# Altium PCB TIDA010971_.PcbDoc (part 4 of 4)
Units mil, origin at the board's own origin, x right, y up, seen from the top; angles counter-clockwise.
Board outline 4500 x 6000 mil, 2 copper layers (F.CU, B.CU), stack 60.617 mil thick; 280 components, 124 nets, 681 pads, 871 vias.
Unrouted connection lines stored in the file: 1.
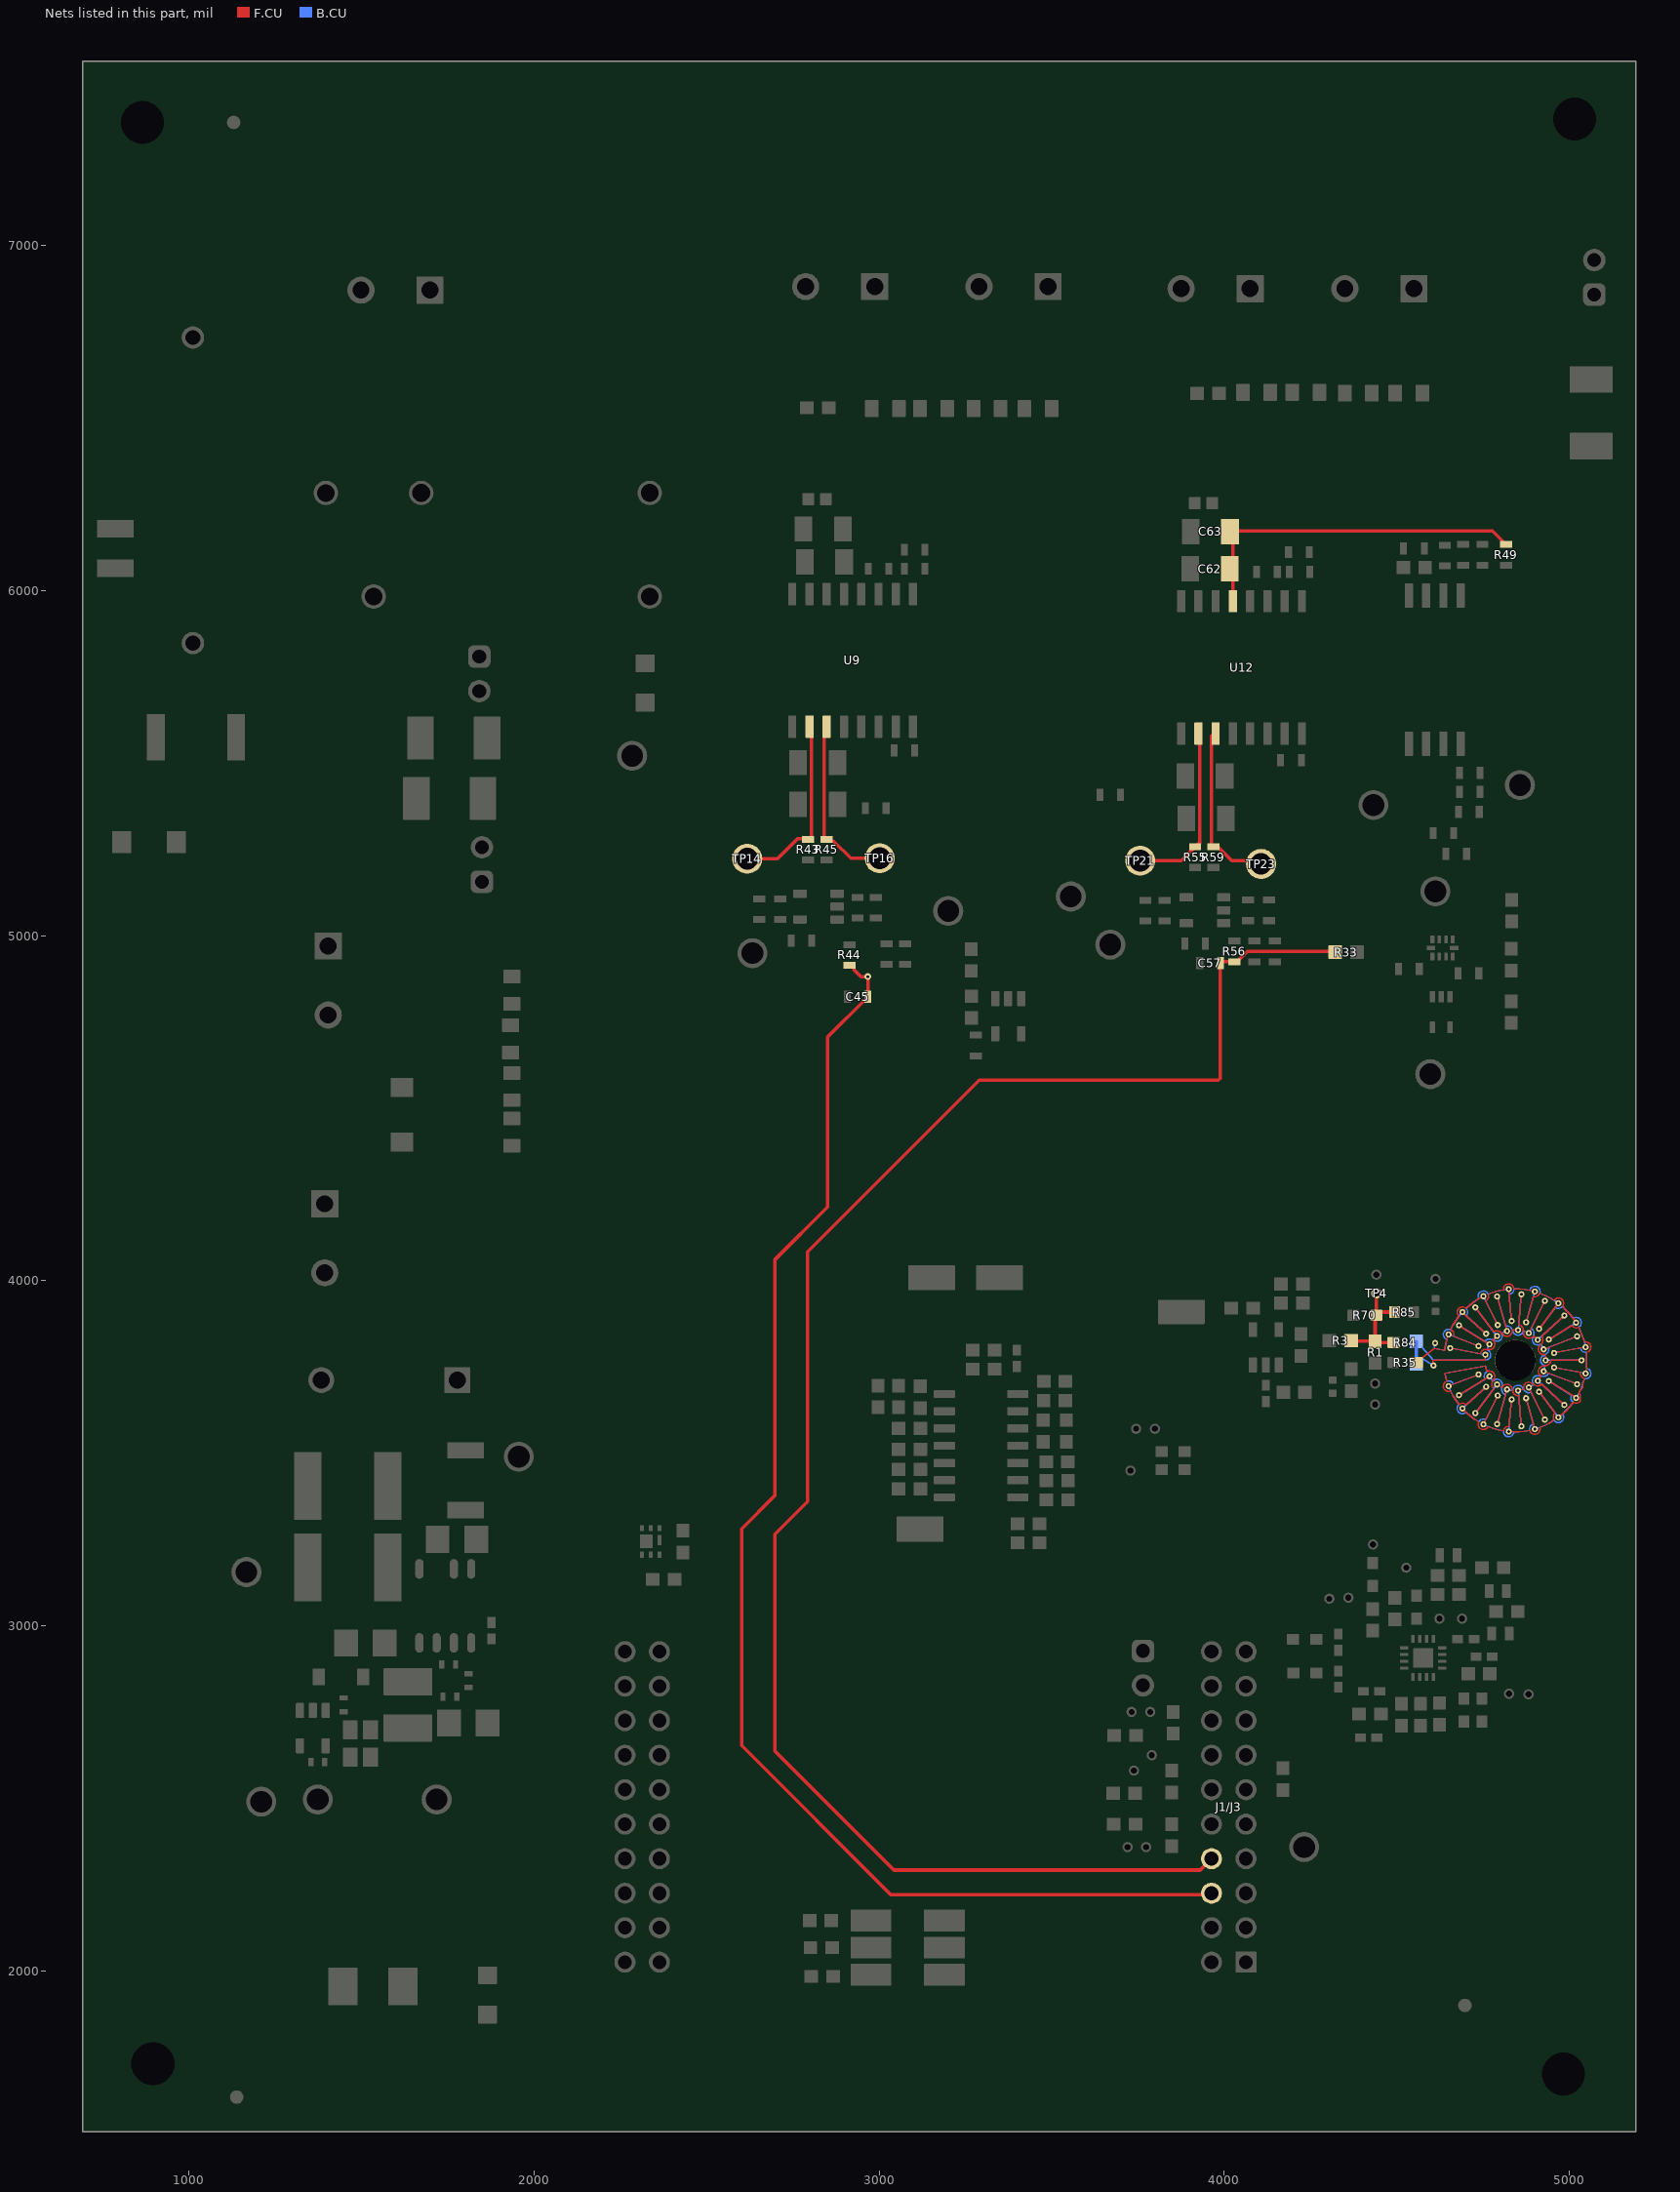
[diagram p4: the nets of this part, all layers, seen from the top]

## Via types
v1: diameter 24, hole 8, F.CU to B.CU, tented both sides, 774 vias
v2: diameter 19.68, hole 7.87, F.CU to B.CU, tented both sides, 97 vias

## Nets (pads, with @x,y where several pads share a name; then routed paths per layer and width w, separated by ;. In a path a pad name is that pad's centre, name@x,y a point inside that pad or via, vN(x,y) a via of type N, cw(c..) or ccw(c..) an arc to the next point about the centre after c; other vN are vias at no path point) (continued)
Rogo-: pad.1 pad.2 pad.3 pad.4 pad.12 pad.13 pad.14 pad.15 pad.16 pad.17 pad.18 pad.19 pad.20 pad.21 pad.22 pad.23 pad.24 pad.25 pad.26 pad.27 pad.28 pad.29 pad.30 pad.31 pad.32 pad.33 pad.34 pad.35 pad.36 pad.37 pad.38 pad.39 pad.40 pad.41 pad.42 pad.43 pad.44 pad.45 pad.46 pad.47 pad.48 pad.49 pad.50 pad.51 pad.52 pad.53 pad.54 pad.55 pad.56 pad.57 pad.58 pad.59 pad.60 pad.61 pad.62 pad.63 pad.64 pad.65 pad.66 pad.67 pad.68 pad.69 pad.70 pad.71 pad.72 pad.73 pad.74 pad.75 pad.Un1 R35.1 | length 11021.8
  F.CU w3.94: R35.1@4571.32,3775.07 4608.15,3804.42 4637.97,3798.84 cw(c4843.17,3769.49) pad.15@4649.88,3844.37 ; 4604.17,3769.36 ccw(c4843.17,3791.8) pad.3@4606.05,3754.35 ; 4605.57,3769.49 4755.18,3769.49 cw(c4843.17,3769.49) pad.12@4756.68,3785.66 ; pad.75@4649.88,3694.61 pad.74@4736.64,3728.22 ; pad.13@4654.31,3804.8 4741.78,3788.45 cw(c4756.68,3785.66) 4760.73,3800.25 cw(c4843.17,3769.49) 4761.52,3802.31 ccw(c4768.36,3815.82) 4777.4,3827.95 cw(c4843.17,3769.49) pad.20@4790.14,3839.71 ; pad.73@4679.82,3668.35 pad.72@4768.36,3723.17 ; pad.17@4679.82,3870.63 pad.16@4768.36,3815.82 ; pad.71@4689.98,3629.85 ccw(c4843.17,3769.49) 4737.47,3591.19 ccw(c4750.77,3583.94) 4764.58,3577.69 ccw(c4843.17,3769.49) 4809.02,3565.04 cw(c4824.04,3563.09) 4825.44,3578.18 pad.62@4832.63,3655.74 ; pad.19@4689.98,3909.14 pad.18@4758.74,3846.46 ; pad.69@4727.39,3616.17 4781.01,3687.18 cw(c4790.14,3699.27) 4778.89,3709.4 cw(c4843.17,3769.49) 4777.4,3711.03 ccw(c4768.36,3723.17) 4761.52,3736.68 cw(c4843.17,3769.49) 4756.68,3753.33 4639.42,3731.41 ccw(c4843.17,3769.49) 4644.93,3708.94 ccw(c4649.88,3694.61) 4655.87,3680.69 ccw(c4843.17,3769.49) 4680.19,3641.41 cw(c4689.98,3629.85) 4701.18,3640.06 pad.70@4758.74,3692.53 ; pad.21@4727.39,3922.81 4781.01,3851.81 cw(c4790.14,3839.71) 4802.96,3847.76 cw(c4843.17,3769.49) 4804.94,3848.75 ccw(c4819.09,3854.13) 4833.95,3857 cw(c4843.17,3769.49) pad.28@4851.29,3857.11 ; pad.14@4736.64,3810.76 4664.02,3838.9 ccw(c4649.88,3844.37) 4655.87,3858.29 cw(c4843.17,3769.49) 4680.19,3897.57 cw(c4689.98,3909.14) 4700.6,3919.96 cw(c4843.17,3769.49) pad.23@4750.77,3955.05 ; pad.67@4750.77,3583.94 pad.66@4792.25,3667.22 ; pad.68@4790.14,3699.27 ccw(c4843.17,3769.49) 4804.94,3690.24 cw(c4819.09,3684.86) 4833.95,3681.99 ccw(c4843.17,3769.49) 4836.15,3681.78 ccw(c4851.29,3681.88) 4852.68,3666.8 pad.61@4860.9,3578.19 ; pad.65@4790.59,3584.7 pad.64@4819.09,3684.86 ; pad.25@4790.59,3954.29 pad.24@4819.09,3854.13 ; pad.22@4792.25,3871.76 4757.53,3941.48 ccw(c4750.77,3955.05) 4764.58,3961.3 cw(c4843.17,3769.49) 4809.02,3973.94 cw(c4824.04,3975.89) 4839.17,3976.74 cw(c4843.17,3769.49) pad.31@4899.9,3968.86 ; pad.63@4824.04,3563.09 ccw(c4843.17,3769.49) 4885.18,3566.51 ccw(c4899.9,3570.12) 4914.31,3574.8 ccw(c4843.17,3769.49) 4955.67,3595.39 cw(c4968.09,3604.08) 4958.95,3616.17 pad.54@4912.02,3678.32 ; pad.27@4824.04,3975.89 pad.26@4832.63,3883.25 ; pad.60@4851.29,3681.88 ccw(c4843.17,3769.49) 4868.31,3685.17 cw(c4882.39,3690.73) 4895.31,3698.61 ccw(c4843.17,3769.49) 4897.07,3699.94 ccw(c4908.2,3710.21) 4919.38,3700.01 pad.53@4985.15,3640.06 ; pad.29@4860.9,3960.8 4852.69,3872.2 cw(c4851.29,3857.11) 4866.19,3854.42 cw(c4843.17,3769.49) 4868.31,3853.82 ccw(c4882.39,3848.26) 4895.31,3840.37 cw(c4843.17,3769.49) pad.36@4908.2,3828.77 ; pad.58@4874.43,3659.61 pad.59@4899.9,3570.12 ; pad.30@4874.43,3879.38 4895.75,3954.29 ccw(c4899.9,3968.86) 4914.31,3964.19 cw(c4843.17,3769.49) 4955.67,3943.59 cw(c4968.09,3934.91) 4979.84,3925.34 cw(c4843.17,3769.49) pad.39@5019.41,3878.61 ; pad.56@4882.39,3690.73 pad.57@4928.81,3597.51 ; pad.32@4882.39,3848.26 pad.33@4928.81,3941.48 ; pad.52@4908.2,3710.21 ccw(c4843.17,3769.49) 4918.56,3724.11 cw(c4925.22,3737.71) 4929.45,3752.24 ccw(c4843.17,3769.49) 4929.86,3754.41 ccw(c4931.16,3769.49) 4946.3,3769.49 pad.45@5035.3,3769.49 ; pad.34@4912.02,3860.66 pad.35@4968.09,3934.91 ; 4919.38,3838.97 cw(c4908.2,3828.77) 4917.39,3816.75 cw(c4843.17,3769.49) 4918.56,3814.87 ccw(c4925.22,3801.28) 4929.45,3786.75 cw(c4843.17,3769.49) pad.44@4931.16,3769.49 ; 4919.4,3838.99 pad.37@4985.15,3898.93 ; pad.48@4925.22,3737.71 pad.49@5022.32,3700.09 ; pad.40@4925.22,3801.28 pad.41@5022.32,3838.9 ; pad.50@4940.3,3709.35 pad.51@5019.41,3660.37 ; pad.38@4940.3,3829.64 5006.52,3870.63 ccw(c5019.41,3878.61) 5026.91,3865.45 cw(c4843.17,3769.49) 5043.6,3822.37 cw(c5046.92,3807.58) 5049.16,3792.59 cw(c4843.17,3769.49) pad.47@5046.92,3731.41 ; pad.46@4955.47,3748.5 5032.02,3734.19 ; pad.42@4955.47,3790.49 pad.43@5046.92,3807.58 ; pad.55@4968.09,3604.08 ccw(c4843.17,3769.49) 5010.96,3647.79 ccw(c5019.41,3660.37) 5031.29,3650.97 5031.29,3669.78 ccw(c5019.41,3660.37) 5026.91,3673.54 ccw(c4843.17,3769.49) 5031.29,3682.44 5039.15,3690.3 5039.15,3701.97 ccw(c4843.17,3769.49) 5043.6,3716.62 cw(c5046.92,3731.41) 5032.03,3734.19
  B.CU w3.94: pad.2@4571.32,3775.07 pad.3@4606.05,3754.35 ; pad.1@4571.32,3808.53 4605.57,3769.49 4755.18,3770.6 ccw(c4756.68,3785.66) 4760.73,3800.25 cw(c4843.17,3769.49) pad.16@4768.36,3815.82 ; pad.4@4610.86,3819.33 ccw(c4843.17,3769.49) 4608.15,3804.42 4637.97,3798.84 cw(c4843.17,3769.49) 4644.93,3830.05 cw(c4649.88,3844.37) 4660.49,3855.19 ; pad.75@4649.88,3694.61 ccw(c4843.17,3769.49) 4680.19,3641.41 ccw(c4689.98,3629.85) 4700.6,3619.03 ccw(c4843.17,3769.49) 4737.47,3591.19 cw(c4750.77,3583.94) 4757.53,3597.51 pad.66@4792.25,3667.22 ; pad.15@4649.88,3844.37 pad.14@4736.64,3810.76 ; pad.13@4654.31,3804.8 pad.12@4756.68,3785.66 ; 4655.87,3858.29 cw(c4843.17,3769.49) pad.19@4689.98,3909.14 ; pad.73@4679.82,3668.35 4755.47,3715.19 ; pad.17@4679.82,3870.63 4755.47,3823.79 ; pad.71@4689.98,3629.85 pad.70@4758.74,3692.53 ; pad.69@4727.39,3616.17 pad.68@4790.14,3699.27 ; pad.21@4727.39,3922.81 pad.20@4790.14,3839.71 ; pad.74@4736.64,3728.22 4664.02,3700.09 ccw(c4649.88,3694.61) 4644.93,3708.94 cw(c4843.17,3769.49) 4639.42,3731.41 4756.68,3753.33 ccw(c4843.17,3769.49) 4761.52,3736.68 ccw(c4768.36,3723.17) 4755.49,3715.2 ; pad.67@4750.77,3583.94 ccw(c4843.17,3769.49) 4809.02,3565.04 ccw(c4824.04,3563.09) 4839.17,3562.25 ccw(c4843.17,3769.49) 4885.18,3566.51 cw(c4899.9,3570.12) 4895.75,3584.7 pad.58@4874.43,3659.61 ; pad.23@4750.77,3955.05 pad.22@4792.25,3871.76 ; 4755.49,3823.79 cw(c4768.36,3815.82) 4777.4,3827.95 cw(c4843.17,3769.49) 4778.89,3829.58 ccw(c4790.14,3839.71) 4802.96,3847.76 cw(c4843.17,3769.49) pad.24@4819.09,3854.13 ; pad.18@4758.74,3846.46 4701.19,3898.93 ccw(c4689.98,3909.14) 4700.6,3919.96 cw(c4843.17,3769.49) 4737.47,3947.8 cw(c4750.77,3955.05) 4764.58,3961.3 cw(c4843.17,3769.49) pad.27@4824.04,3975.89 ; pad.72@4768.36,3723.17 ccw(c4843.17,3769.49) 4778.89,3709.4 cw(c4790.14,3699.27) 4802.96,3691.22 ccw(c4843.17,3769.49) 4804.94,3690.24 ccw(c4819.09,3684.86) 4814.95,3670.3 pad.65@4790.59,3584.7 ; pad.25@4790.59,3954.29 4814.94,3868.71 cw(c4819.09,3854.13) 4833.95,3857 cw(c4843.17,3769.49) 4836.15,3857.21 ccw(c4851.29,3857.11) 4866.19,3854.42 cw(c4843.17,3769.49) pad.32@4882.39,3848.26 ; pad.64@4819.09,3684.86 ccw(c4843.17,3769.49) 4836.15,3681.78 cw(c4851.29,3681.88) 4866.19,3684.57 ccw(c4843.17,3769.49) 4868.31,3685.17 ccw(c4882.39,3690.73) 4889.14,3677.17 pad.57@4928.81,3597.51 ; pad.63@4824.04,3563.09 pad.62@4832.63,3655.74 ; pad.26@4832.63,3883.25 4825.44,3960.8 ccw(c4824.04,3975.89) 4839.17,3976.74 cw(c4843.17,3769.49) 4885.18,3972.48 cw(c4899.9,3968.86) 4914.31,3964.19 cw(c4843.17,3769.49) pad.35@4968.09,3934.91 ; pad.60@4851.29,3681.88 pad.61@4860.9,3578.19 ; pad.28@4851.29,3857.11 pad.29@4860.9,3960.8 ; pad.30@4874.43,3879.38 pad.31@4899.9,3968.86 ; pad.56@4882.39,3690.73 ccw(c4843.17,3769.49) 4897.07,3699.94 cw(c4908.2,3710.21) 4917.39,3722.24 ccw(c4843.17,3769.49) 4918.56,3724.11 ccw(c4925.22,3737.71) 4939.34,3732.24 pad.49@5022.32,3700.09 ; 4889.14,3861.81 cw(c4882.39,3848.26) 4895.31,3840.37 cw(c4843.17,3769.49) 4897.07,3839.04 ccw(c4908.2,3828.77) 4917.39,3816.75 cw(c4843.17,3769.49) pad.40@4925.22,3801.28 ; 4889.15,3861.83 pad.33@4928.81,3941.48 ; pad.59@4899.9,3570.12 ccw(c4843.17,3769.49) 4955.67,3595.39 ccw(c4968.09,3604.08) 4979.84,3613.65 ccw(c4843.17,3769.49) 5010.96,3647.79 cw(c5019.41,3660.37) 5006.52,3668.35 pad.50@4940.3,3709.35 ; pad.52@4908.2,3710.21 pad.53@4985.15,3640.06 ; pad.36@4908.2,3828.77 pad.37@4985.15,3898.93 ; pad.54@4912.02,3678.32 pad.55@4968.09,3604.08 ; pad.34@4912.02,3860.66 4958.95,3922.81 ccw(c4968.09,3934.91) 4979.84,3925.34 cw(c4843.17,3769.49) 5010.96,3891.2 cw(c5019.41,3878.61) 5026.91,3865.45 cw(c4843.17,3769.49) pad.43@5046.92,3807.58 ; pad.48@4925.22,3737.71 ccw(c4843.17,3769.49) 4929.86,3754.41 cw(c4931.16,3769.49) 4929.86,3784.58 ccw(c4843.17,3769.49) 4929.45,3786.75 ccw(c4925.22,3801.28) 4939.34,3806.75 pad.41@5022.32,3838.9 ; pad.44@4931.16,3769.49 pad.45@5035.3,3769.49 ; pad.38@4940.3,3829.64 pad.39@5019.41,3878.61 ; pad.46@4955.47,3748.5 pad.47@5046.92,3731.41 ; pad.42@4955.47,3790.49 5032.02,3804.8 ; pad.51@5019.41,3660.37 ccw(c4843.17,3769.49) 5043.6,3716.62 ccw(c5046.92,3731.41) 5049.16,3746.39 ccw(c4843.17,3769.49) 5049.16,3792.59 cw(c5046.92,3807.58) 5032.03,3804.8
  B.CU w10: pad.2@4556.56,3759.32 pad.1@4556.56,3824.28
Rogo_input: R1.1 R3.1 R70.1 R84.2 R85.2 TP4.1 | length 322.4
  F.CU w10: R3.1@4367.31,3826.3 4369.11,3824.5 R1.1@4437,3824.5 ; TP4.1@4440.66,3963.62 R70.1@4440.66,3899.86 ; R84.2@4490.54,3821 4440.5,3821 R1.1@4437,3824.5 ; R85.2@4493.13,3909.14 4449.94,3909.14 R70.1@4440.66,3899.86 ; R1.1@4437,3824.5 4437,3896.2 R70.1@4440.66,3899.86
V_Gap: C57.1 J1/J3.24 R33.2 R56.2 | length 4992.3
  F.CU w10: J1/J3.24@3962.78,2325 3929.78,2292 3042.7,2292 2697.61,2637.08 2697.61,3265.38 2792.24,3360.01 2792.24,4083.57 3289.67,4581 3982.89,4581 3988.75,4586.86 C57.1@3988.75,4920.57 ; C57.1@3988.75,4924.66 R56.2@4029.19,4924.66 4037.06,4924.66 4067.06,4954.66 4319.21,4954.66 R33.2@4321.52,4952.34
V_String: C45.1 J1/J3.23 R44.2 | length 3993.3
  F.CU w10: R44.2@2914.22,4914.06 2921.72,4914.06 2926.72,4909.06 2926.72,4901.56 2947.08,4881.2 v2(2966.88,4881.2) 2967.27,4880.8 C45.1@2967.27,4823.04 2850.5,4706.27 2850.5,4213.78 2697,4060.28 2697,3377 2601,3281 2601,2653 3033.28,2220.72 3958.5,2220.72 J1/J3.23@3962.78,2225
VCC_iso_AMC23C12: C62.1 C63.1 R49.1 U12.5 | length 999.9
  F.CU w10: C63.1@4016.41,6171.36 4018.62,6173.57 4776.63,6173.57 R49.1@4816.53,6133.66 ; C63.1@4021.44,6150.46 4024.85,6147.05 U12.5@4024.85,5969.52
VGap_Diff_N: R55.1 TP21.1 U12.10 | length 512.7
  F.CU w10: TP21.1@3756.18,5217.29 3875.11,5217.29 R55.1@3915.44,5257.62 3924.85,5267.03 3928.21,5267.03 3928.21,5582.29 U12.10@3924.85,5585.66
VGap_Diff_P: R59.1 TP23.1 U12.11 | length 497.6
  F.CU w10: U12.11@3974.85,5585.66 3967.92,5578.73 3962.54,5578.73 3962.54,5263.01 R59.1@3967.92,5257.62 3981.11,5257.62 4021.44,5217.29 4097.37,5217.29 TP23.1@4106.48,5208.18
VString_Diff_N: R43.1 TP14.1 U9.10 | length 536.7
  F.CU w10: TP14.1@2617.42,5222.83 2705.09,5222.83 2763.27,5281 2802.94,5281 2802.94,5600.8 U9.10@2797.75,5605.99
VString_Diff_P: R45.1 TP16.1 U9.11 | length 513.4
  F.CU w10: U9.11@2847.75,5605.99 2840.94,5599.18 2840.94,5573.41 2840.18,5572.65 2840.18,5279.52 R45.1@2847.75,5279.52 2852.75,5274.52 2867.43,5274.52 2917.59,5224.36 TP16.1@3001.1,5224.36
pads on no net: FID1.1 FID2.1 FID3.1 J1/J3.2 J1/J3.3 J1/J3.4 J1/J3.5 J1/J3.7 J1/J3.9 J1/J3.10 J1/J3.28 J2/J4.11 J2/J4.12 J2/J4.13 J2/J4.14 J2/J4.15 J2/J4.16 J2/J4.17 J2/J4.18 J2/J4.19 J2/J4.31 J2/J4.32 J2/J4.38 MH1.1 MH2.1 MH3.1 MH4.1 Q1.0 SH-J1.0 SH-J5.0 SH-J6.0 U3.6 U4.6 U5.3 U5.4 U7.1 U9.4 U9.14 U12.4 U12.14

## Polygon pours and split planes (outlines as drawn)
AGND on F.CU "F.CU_AGND_P104" (solid, pour order 104): 2775.43,4299.88 2825.14,4299.88 4985.15,4299.88 4985.15,5584.54 4948.34,5621.35 2203.65,5621.35 2195,5630 2195,3037.38 2073,2915.38 2073,1561 2630,1561 2630,4299.88 2702.4,4299.88
AGND on F.CU "F.CU_AGND_P103" (solid, pour order 103): 2602.41,4284 2602.41,1950.52 2599.89,1948 2559,1948 2559,1564 2560,1565 5162,1565 5162,4280 5168,4286
Primary on F.CU "F.CU_PRIMARY_P094" (solid, remove dead copper, pour order 94): 1103,5671.5 1440.5,6009 1721.41,6009 1721.41,4533 1103,4533
NetC20_2 on F.CU "F.CU_NETC20_2_P087" (solid, remove dead copper, pour order 87): 1747.29,2986.23 1741.65,2783.34 1727.87,2781.37 1586.4,2828.84 1532.49,2911.26 1532.49,2986.23
AGND on F.CU "F.CU_AGND_P106" (solid, pour order 106): 937.37,2233.06 950.27,2245.96 2086.34,2245.96 2086.34,1563.9 2087.84,1562.4 927.84,1562.4
no net on F.CU "F.CU_NONET_P101" (solid, remove dead copper, pour order 101): 5168,4286 5166,4284 2602.41,4284
AGND on F.CU "F.CU_AGND_P107" (solid, remove dead copper, pour order 107): 1343.47,4248.09 1533.08,4437.69 1729.24,4437.69 1899,4267.93 1899,3667.87 1744.47,3667.87 1633,3788 1452,3969 1336,3969 1336,4255.29 1343.47,4262.76
AGND on F.CU "F.CU_AGND_P098" (solid, remove dead copper, pour order 98): 937.53,2198 960.53,3546 1429,3546 1429,2783.14 1815.61,2396.53 1815.61,2213.93 1799.68,2198 968,2198
no net on F.CU "F.CU_NONET_P099" (solid, remove dead copper, pour order 99): 1902.01,3395.11 1955.9,3341.22 1955.9,3192.5 1771.73,3192.5 1712.8,3251.43 1712.8,3370.78 1737.13,3395.11
RelayControl on F.CU "F.CU_RELAYCONTROL_P096" (solid, remove dead copper, pour order 96): 1081,6262 1404,6262 1489.69,6262 1710,6638 1898.44,6981.21 1898.44,7276 1432.5,7276 961.48,6790.91
NetD2_2 on F.CU "F.CU_NETD2_2_P092" (solid, remove dead copper, pour order 92): 1901.34,3399.61 1955.22,3345.72 1955.22,3197 1771.06,3197 1712.13,3255.93 1712.13,3375.28 1736.46,3399.61
5v_led on F.CU "F.CU_5V_LED_P091" (solid, remove dead copper, pour order 91): 1417.4,2772.93 1462.83,2772.93 1462.83,2763.78 1496.79,2729.83 1496.79,2514.85 1587.11,2424.54 1801.42,2424.54 1801.42,2762.66 1801.81,2763.05 1791.93,2772.93 1712.13,2772.93 1712.13,2803.54 1685.98,2829.69 1548.83,2829.69 1548.83,2856.58 1508.11,2897.3 1403.26,2897.3 1403.26,2821.05 1378.68,2796.48 1378.68,2726.38 1417.4,2726.38
HVIN on F.CU "F.CU_HVIN_P090" (solid, remove dead copper, pour order 90): 1536.35,3490.16 1689.97,3490.16 1689.97,3317.06 1758.97,3248.06 1758.97,3200.5 1822.22,3200.5 1832.91,3189.81 1832.91,3114.08 1536.35,3114.08
GND_iso_AMC23C12 on F.CU "F.CU_GND_ISO_AMC23C12_P064" (solid, remove dead copper, pour order 64): 4139.71,6098.96 4172.46,6131.71 4205.69,6131.71 4203.76,6129.79 4203.76,6003.87 4185.77,5985.87 4165.7,5985.87 4165.7,5998.29 4139.99,6023.99
NetC34_2 on F.CU "F.CU_NETC34_2_P043" (solid, remove dead copper, pour order 43): 3035.25,5996.9 3035.25,6018.43 3009.09,6044.59 3009.09,6113.87 3038.1,6142.87 3086.64,6142.87 3097.38,6132.13 3097.38,6058.01 3041.84,6002.47 3041.84,5996.9
NetC34_2 on F.CU "F.CU_NETC34_2_P068" (solid, remove dead copper, pour order 68): 3054.58,6982.13 3057.53,6979.17 3057.53,6801.63 2885.6,6801.63 2809.38,6725.4 2809.38,5947.52 2711.84,5947.52 2682.69,5976.67 2682.69,6979.16
GND_iso_AMC23C12 on F.CU "F.CU_GND_ISO_AMC23C12_P066" (solid, remove dead copper, pour order 66): 4129.66,6966.76 4132.62,6963.81 4132.62,6786.26 3960.68,6786.26 3952.18,6777.76 3953.39,6776.56 3953.39,5927.19 3823.46,5927.19 3810.06,5940.6 3810.06,6964.22
AGND on B.CU "B.CU_AGND_P102" (solid, remove dead copper, pour order 102): 2775.43,4299.88 2825.14,4299.88 4985.15,4299.88 4985.15,5584.54 4948.34,5621.35 2203.65,5621.35 2195,5630 2195,3037.38 2073,2915.38 2073,1561 2614.13,1561 2614.13,4299.88 2702.4,4299.88
AGND on B.CU "B.CU_AGND_P105" (solid, pour order 105): 2602.41,4284 2602.41,1950.52 2599.89,1948 2559,1948 2559,1564 2560,1565 5162,1565 5162,4280 5168,4286
Primary on B.CU "B.CU_PRIMARY_P110" (solid, remove dead copper, pour order 110): 1110.71,5683.95 1448.21,6021.45 1729.12,6021.45 1729.12,4545.45 1110.71,4545.45
GND_iso_AMC23C12 on B.CU "B.CU_GND_ISO_AMC23C12_P073" (solid, remove dead copper, pour order 73): 3817.14,6015.22 4560.4,6013.84 4561.78,6015.22 4561.78,6150.76 3817.14,6150.76
AGND on B.CU "B.CU_AGND_P109" (solid, remove dead copper, pour order 109): 2227.52,4180 2227.52,3671.86 2223.53,3667.87 1749.14,3671.86 1633,3788 1452,3969 1293.59,3969 1293.59,4180
AGND on B.CU "B.CU_AGND_P108" (solid, remove dead copper, pour order 108): 1469.13,3969 1289,3969 1116,3796 1116,3515.61 964.92,3515.61 960.53,3520 966,3525.47 966,4284 1469.13,4284
AGND on B.CU "B.CU_AGND_P100" (solid, remove dead copper, pour order 100): 937.53,2198 960.53,3546 1429,3546 1429,2783.14 1815.61,2396.53 1815.61,2213.93 1799.68,2198 968,2198
AGND on B.CU "B.CU_AGND_P055" (solid, pour order 55): 937.53,2235.67 950.44,2248.57 2148.5,2248.57 2148.5,1565 928,1565
RelayControl on B.CU "B.CU_RELAYCONTROL_P097" (solid, remove dead copper, pour order 97): 1090.2,6262 1501.64,6262 1898.44,6981.21 1898.44,7276 1991,7276 1432.5,7276 958.96,6802.47
5v_led on B.CU "B.CU_5V_LED_P093" (solid, remove dead copper, pour order 93): 1462.83,2771.57 1462.83,2773.91 1462.83,2764.77 1496.79,2730.81 1496.79,2593.04 1587.86,2501.97 1801.42,2501.97 1801.42,2763.64 1801.81,2764.03 1791.93,2773.91 1712.13,2773.91 1655.37,2830.68 1548.83,2830.68 1462.83,2830.68 1462.83,2788.8
HVIN on B.CU "B.CU_HVIN_P089" (solid, remove dead copper, pour order 89): 1528.47,3490.16 1688.27,3490.16 1688.27,3317.06 1757.27,3248.06 1757.27,3200.5 1820.52,3200.5 1831.22,3189.81 1831.22,3126.3 1528.47,3126.3
NetD2_2 on B.CU "B.CU_NETD2_2_P088" (solid, remove dead copper, pour order 88): 1901.34,3399.61 1955.22,3345.72 1955.22,3197 1771.06,3197 1712.13,3255.93 1712.13,3375.28 1736.46,3399.61
5v_led on B.CU "B.CU_5V_LED_P086" (solid, remove dead copper, pour order 86): 1447.31,2771.63 1447.31,2773.98 1447.31,2764.83 1481.26,2730.87 1481.26,2593.1 1572.33,2502.03 1785.89,2502.03 1785.89,2763.7 1786.28,2764.09 1776.4,2773.98 1696.6,2773.98 1639.84,2830.74 1533.3,2830.74 1447.31,2830.74 1447.31,2788.86

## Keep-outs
Keep-Out Layer:
  lines w0: 4389.58,5337.35 4389.58,5337.35
  text ".Layer_Name" at 1269,675.51 h60

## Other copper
F.CU:
  pour cut-out: 1844.52,4262.09 1896.22,4210.39 2005.69,4210.39 2005.69,4990.67 1991.86,5004.5 1850.13,5004.5 1844.52,4994.22
  text ".Layer_Name" at 1269,675.51 h60
B.CU:
  text ".Layer_Name" at 1269,675.51 h60

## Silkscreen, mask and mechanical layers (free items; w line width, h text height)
Top Overlay:
  drawing of 33 lines, arcs and shapes, not listed
  text "DANGER HIGH VOLTAGE" at 3465,7474 h78.74 r180
  text "110-250 VAC 12A" at 1889.06,7416 h50 r180
  text "110-250 VAC" at 3643.5,7333 h50 r180
  text "110-250 VAC" at 4705.06,7331 h50 r180
  text "110-250 VAC" at 4195.45,7321.66 h50 r180
  text "Relay Control" at 1911,7176.34 h50 r180
  text "ARC +" at 4552.46,7145.07 h50 r180
  text "Neutral" at 3036,7133 h50 r180
  text "ARC -" at 4068.89,7132.27 h50 r180
  text "Primary" at 3571.14,7128.46 h50 r180
  text "Neutral" at 4924,6794 h40 r90
  text "Auto-Labeling" at 3004.71,6399.56 h40
  text "DANGER        HIGH VOLTAGE" at 3274.85,6003.87 h30
  text "RC Snubber" at 766,5914 h50 r270
  text "CAUTION     HOT SURFACE" at 1217,5557.26 h30 r270
  text "Primary arc+" at 2031,5503 h30 r90
  text "Primary" at 2037.01,5130.73 h30 r90
  text "110-250 VAC" at 956,5101.06 h50 r270
  text "Primary" at 1152.59,5033 h50 r270
  text "DANGER HIGH VOLTAGE" at 816,5005 h78.74 r270
  text "1p67" at 3349,4903.72 h30
  text "Line Voltage" at 2480,4596.66 h50
  text "Arc Gap Voltage" at 3572.53,4584.79 h50
  text "Voltage Sense" at 2056,4482 h30 r90
  text "Auto labeling for arc data collection" at 3211.9,4461 h30
  text "Arc Comp" at 4499.98,4387.66 h50
  text "Neutral" at 1162,4292.64 h50 r270
  text "Current Sense" at 4034.85,4206.52 h50
  text "TLV387 Hybrid Integrator" at 3989.37,4142 h30
  text "Current-LPF" at 3452.85,3859 h30
  text "Voltage" at 2719.74,3842.36 h30
  text "PCB di/dt sensor 3mm ID 12mm OD" at 4647.22,3420.93 h30
  text "Relay Control" at 2240.65,3328.76 h30
  text "Current-BPF" at 3536.65,3232.32 h30
  text "Midsupply Buffer" at 2762.66,3170.94 h30
  text "TLV9054 Quad Amp" at 3010.54,3010.36 h30
  text "PA14" at 3575.35,2918.09 h30
  text "1MHz-10MHz" at 5015.13,2865.13 h30 r90
  text "PA13" at 3581.49,2809.13 h30
  text "Relay GPIO PA11" at 2448.93,2719.79 h30
  text "Freq" at 4132.78,2711.81 h30
  text "Current-LPF PA15" at 3139.37,2631 h30
  text "Comp Arc Latch PA10" at 2446.12,2617.43 h30
  text "Comp Extinguished PA31" at 2432.33,2541 h30
  text "LOG" at 4225.12,2510.18 h30
  text "Current-BPF PA16" at 3139.37,2493.78 h30
  text "Comp Arc Gap PA28" at 2429.35,2432.5 h30
  text "Voltage PB16" at 3199.78,2405.23 h30
  text "LOG300 High Frequency Sensing" at 4354.34,2383.44 h30
  text "Comp Ext latch PB1" at 2435.35,2341 h30
  text "Isolated Arc Gap Voltage PB15" at 2894.89,2292.53 h30
  text "Power Supply 3.3v 30mA" at 1060.66,2239.26 h40
  text "Isolated Voltage PB14" at 3174.71,2217.73 h30
  text "PB5" at 2432.33,2131 h30
  text "PB4" at 2436.8,2031 h30
  text "Power" at 3275.5,1971.38 h30
  text "AGND" at 3766.13,1740.68 h30 r90
  text ".PRJ_Title" at 2517,1617 h200
  text "Rev..PCB_Rev-" at 3485.5,1617 h108.27
  text ".PRJ_Number" at 1381,1607 h200
  text ".Layer_Name" at 1269,675.51 h60
Bottom Overlay:
  text "DANGER HIGH VOLTAGE" at 1469.13,3744 h78.74 r270
  text ".Layer_Name" at 1269,675.51 h60
Top Paste:
  text ".Layer_Name" at 1269,675.51 h60
Bottom Paste:
  text ".Layer_Name" at 1269,675.51 h60
Top Solder:
  text ".Layer_Name" at 1269,675.51 h60
  text ".Layer_Name" at 1269,675.51 h60
Bottom Solder:
  text ".Layer_Name" at 1269,675.51 h60
Drill Guide:
  text ".Layer_Name" at 1269,675.51 h60
M1 Board Outline:
  the board outline again, w10
  text ".Layer_Name" at 1269,675.51 h60
M2 Board Dimensions:
  rectangle: 692,1259 817,1384
  rectangle: 817,1134 1192,1259
  lines w7: 692,1259 1692,1259 ; 817,1134 817,1384 ; 942,1134 942,1384 ; 1192,1134 1192,1384 ; 1442,1134 1442,1384 ; 692,1134 1692,1134 1692,1384 692,1384 692,1134
  text ".Layer_Name" at 1269,675.51 h60
M3 3D STEP Top:
  text ".Layer_Name" at 1269,675.51 h60
M4 3D STEP Bottom:
  text ".Layer_Name" at 1269,675.51 h60
M5 Assembly Top:
  lines w10: 400,603.83 7000,603.83 ; 400,807.17 7002,807.17 ; 400,1010.5 400,400.5 4405,400.5 7002,400.5 7002,1010.5 400.5,1010.5 400.5,400.5 1976,400.5 ; 2865,400.5 2865,1010.5 ; 4132,807.17 4132,1010.5 ; 4972,807.17 4972,1010.5 ; 5594,394 5594,596.83
  text "COMPONENTS MARKED 'DNP' SHOULD NOT BE POPULATED." at 1845.5,1215.5 h60
  text "ASSEMBLY VARIANT:" at 1845,1100 h60
  text ".VariantName" at 2881,1100 h60
  text "PCB VIEWED FROM TOP SIDE" at 463.5,878.33 h60
  text "BOARD #:" at 2940,878.33 h60
  text ".PRJ_Number" at 3485.5,878.33 h60
  text "REV:" at 4330,878.33 h60
  text ".PCB_Rev" at 4621.5,878.33 h60
  text "SVN REV:" at 5168,878.33 h60
  text ".VersionControl_RevNumber" at 5674,878.33 h60
  text "TID #:" at 2940,675 h60
  text ".TID" at 3485.5,675 h60
  text "PLOT NAME =" at 463.5,469.66 h60
  text ".plot_File_Name" at 1269,469.66 h60
  text "GENERATED    :" at 2942,469.66 h60
  text ".Print_Date" at 3811.5,469.66 h60
  text ".Print_Time" at 4540.5,469.66 h60
  text "TEXAS INSTRUMENTS" at 5805,469.66 h60
M6 Assembly Bottom:
  lines w10: 399.5,806.67 7001.5,806.67 ; 401.5,603.33 7001.5,603.33 ; 1807.5,393.5 1807.5,596.33 ; 2429.5,806.67 2429.5,1010 ; 3269.5,806.67 3269.5,1010 ; 4536.5,400 4536.5,1010 ; 5425.5,400 7001,400 7001,1010 399.5,1010 399.5,400 2996.5,400 7001.5,400 7001.5,1010
  text "COMPONENTS MARKED 'DNP' SHOULD NOT BE POPULATED." at 6794,1216 h60
  text ".VariantName" at 5750,1100 h60
  text "ASSEMBLY VARIANT:" at 6789,1100 h60
  text ".VersionControl_RevNumber" at 1727.5,877.83 h60
  text "SVN REV:" at 2233.5,877.83 h60
  text ".PCB_Rev" at 2780,877.83 h60
  text "REV:" at 3071.5,877.83 h60
  text ".PRJ_Number" at 3916,877.83 h60
  text "BOARD #:" at 4461.5,877.83 h60
  text "PCB VIEWED FROM BOTTOM SIDE" at 6938,877.83 h60
  text ".TID" at 3916,674.5 h60
  text "TID #:" at 4461.5,674.5 h60
  text "TEXAS INSTRUMENTS" at 1596.5,469.16 h60
  text ".Print_Time" at 2861,469.16 h60
  text ".Print_Date" at 3590,469.16 h60
  text "GENERATED    :" at 4459.5,469.16 h60
  text ".plot_File_Name" at 6132.5,469.16 h60
  text "PLOT NAME =" at 6938,469.16 h60
M9 Title Sheet:
  drawing of 57 lines, arcs and shapes, not listed
  text "1" at 1431.84,9570.5 h70
  text "2" at 3927.5,9570.5 h70
  text "3" at 6416.84,9570.5 h70
  text "4" at 8923.51,9570.5 h70
  text "5" at 11422.5,9570.5 h70
  text "6" at 13927.5,9570.5 h70
  text "A" at 275.5,8427.5 h70
  text "A" at 15075.5,8427.5 h70
  text "B" at 275.5,6047.5 h70
  text "B" at 15075.5,6047.5 h70
  text "C" at 275.5,3672.5 h70
  text "C" at 15075.5,3672.5 h70
  text "PROJECT TITLE:" at 12035.5,1811.5 h45
  text ".PRJ_Title" at 12085.5,1678.17 h70
  text "DESIGNED FOR:" at 12035.5,1510.5 h45
  text ".PRJ_Customer" at 12085.5,1370.5 h70
  text "D" at 275.5,1302.5 h70
  text "D" at 15075.5,1302.5 h70
  text "FILE NAME:" at 12035.5,1210.5 h45
  text ".PCB_File_Name_No_Path" at 12085.5,1090.5 h70
  text "Texas Instruments (TI) and/or its licensors do not warrant the accuracy or completeness of this specification" at 7066,928.66 h45
  text "ENGINEER:" at 12035.5,920.5 h45
  text "LAYOUT BY:" at 13540.5,920.5 h45
  text "or any information contained therein. TI and/or its licensors do not warrant that this design will meet" at 7021.01,816 h45
  text ".PRJ_Engineer" at 12085.5,765.51 h70
  text ".PCB_Layout" at 13591,765.51 h70
  text "the specifications, will be suitable for your application or fit for any particular purpose, or will operate in" at 7021.01,703.33 h45
  text ".Layer_Name" at 1269,675.51 h60
  text "ALTIUM DESIGNER VERSION:" at 13540.5,610.5 h45
  text "an implementation. TI and/or its licensors do not warrant that the design is production worthy. You should" at 7021.01,590.67 h45
  text "completely validate and test your design implementation to confirm the system functionality for your application." at 7066,478 h45
  text ".print_Scale" at 12085.5,477.17 h70
  text ".Application_BuildNumber" at 13591,477.17 h70
  text "1" at 1431.84,270.5 h70
  text "2" at 3927.5,270.5 h70
  text "3" at 6416.84,270.5 h70
  text "4" at 8923.51,270.5 h70
  text "5" at 11422.5,270.5 h70
  text "6" at 13927.5,270.5 h70
M10 Fab Notes:
  drawing of 189 lines, arcs and shapes, not listed
  text "DESIGN INFORMATION" at 13074.02,7890.17 h60
  text "MIN. TRACK WIDTH:" at 12429.46,7758.05 h60
  text "8" at 13525.7,7758.05 h60
  text "MIL" at 13680.46,7758.05 h60
  text "7.874" at 13359.32,7636.36 h60
  text "MIN. CLEARANCE:" at 12429.46,7633.92 h60
  text "MIL" at 13680.46,7633.92 h60
  text "MIN. VIA PAD SIZE:" at 12429.46,7509.8 h60
  text "24" at 13495.71,7509.8 h60
  text "MIL" at 13680.46,7509.8 h60
  text "0.05mm (2MIL)" at 13124.46,7379.9 h60
  text "MINIMUM ANNULAR RING" at 12100.23,7371.67 h60
  text "EXTERNAL" at 13832.46,7371.67 h60
  text "PER" at 12300.23,7261.55 h60
  text "IPC-D-275 CLASS 2 LEVEL C" at 12520.23,7261.54 h60
  text "MIL, HOLES" at 14008.46,7161.07 h60
  text "+/-" at 13616,7152.48 h60
  text "+/-" at 14470,7152.48 h60
  text "REGISTRATION TOLERANCES:" at 12100.23,7151.42 h60
  text "METAL" at 13300,7151.42 h60
  text "5" at 13876.2,7151.42 h60
  text "3" at 14709.2,7151.42 h60
  text "MIL" at 14825.46,7151.42 h60
  text "HOLE SIZE TOLERANCE (UNLESS OTHERWISE SPECIFIED):" at 12100.23,7053.1 h60
  text "+/-" at 14470,7050.23 h60
  text "3" at 14709.2,7049.17 h60
  text "MIL" at 14825.46,7049.17 h60
  text "MATERIAL:" at 12025.46,6911.52 h60
  text "FR-4 High Tg" at 13011.9,6783 h60
  text "X" at 12867.46,6775.01 h60
  text "FR-4" at 12446.46,6770.49 h60
  text "OTHER" at 13934.46,6770.49 h60
  text "62 MIL (1.6mm) +/-10%" at 12766.56,6627.46 h60
  text "X" at 12646.46,6625.01 h60
  text "THICKNESS:" at 12100.23,6619.24 h60
  text "OTHER" at 14051.46,6619.24 h60
  text "TOLERANCE:" at 12100.23,6480.92 h60
  text "X" at 12948.46,6480.92 h60
  text "ANSI IPC-6012 TYPE 3 CLASS 2" at 13126.48,6480.92 h60
  text "OTHER +/-" at 13126.46,6336.73 h60
  text "BOW & TWIST:" at 12100.23,6191.54 h60
  text "X" at 12948.46,6191.54 h60
  text "ANSI IPC-6012 TYPE 3 CLASS 2" at 13126.48,6191.54 h60
  text "OTHER +/-" at 13126.46,6044.85 h60
  text "DRILLING:" at 12025.46,5914.23 h60
  text "NC_DRILL FILES" at 13786.46,5809.04 h60
  text "REFERENCE:" at 12100.23,5805.1 h60
  text "X" at 12757.46,5805.01 h60
  text "AS SHOWN" at 12935.46,5805.1 h60
  text "X" at 13658.46,5805.1 h60
  text "OTHER" at 14084.46,5662.85 h60
  text "PTH COPPER THICKNESS:" at 12099.91,5659.32 h60
  text "X" at 13239.14,5659.32 h60
  text "20-30 um" at 13367.14,5659.32 h60
  text "BOARD FINISH:" at 12025.46,5511.73 h60
  text "SILKSCREEN:" at 12180.68,5401.6 h60
  text "X" at 13138.46,5401.6 h60
  text "TOP" at 13255.46,5401.6 h60
  text "X" at 13648.46,5401.6 h60
  text "BOTTOM" at 13766.46,5401.6 h60
  text "SILKSCREEN COLOR:" at 12180.68,5246.41 h60
  text "X" at 13137.46,5246.41 h60
  text "WHITE" at 13255.46,5246.41 h60
  text "OTHER" at 13766.46,5246.41 h60
  text "X" at 13268.46,5102.96 h60
  text "GREEN" at 13386.46,5102.96 h60
  text "OTHER" at 14004.46,5102.96 h60
  text "SOLDER RESIST COLOR:" at 12180.68,5096.1 h60
  text "X" at 13268.46,4948.71 h60
  text "MATTE" at 13386.46,4948.71 h60
  text "SEMI-GLOSS" at 14004,4948.07 h60
  text "IMMERSION GOLD (ENIG)" at 13086.46,4775.94 h60
  text "ENEPIG" at 14424,4768.72 h60
  text "SURFACE FINISH:" at 12025.46,4767.72 h60
  text "X" at 12908.46,4767.72 h60
  text "IMM. TIN/SILVER OR EQUIV" at 12355,4630.4 h60
  text "OTHER" at 13786.46,4626.47 h60
  text "ARRAY/PANEL:" at 12025.46,4471.09 h60
  text "CUT AND TRIM PER M1 BOARD OUTLINE" at 13086.46,4462.87 h60
  text "N.C. ROUTE" at 13086.46,4326.9 h60
  text "X" at 13774.46,4326.9 h60
  text "V. SCORE" at 13952.46,4326.9 h60
  text "CERTIFICATION:" at 12025.46,4197.77 h60
  text "MATERIALS AND WORKMANSHIP FOR ALL PCBS" at 12750.46,4197.77 h60
  text "TO MEET OR EXCEED THE REQUIREMENTS OF:" at 12750.46,4103.71 h60
  text "X" at 12387.97,3975.08 h60
  text "ANSI IPC-A-600F CLASS ->" at 12515.96,3975.08 h60
  text "X" at 14163.97,3975.08 h60
  text "2" at 14273.96,3975.08 h60
  text "1" at 13958.96,3973.58 h60
  text "3" at 14627.96,3973.58 h60
  text "X" at 13199.97,3827.39 h60
  text "RoHS" at 13327.96,3827.39 h60
  text "OTHER" at 13972.36,3827.39 h60
  text "PER ORDER" at 14369.42,3827.39 h60
  text "ALL BOARDS MUST MEET OR EXCEED UL94-V0 REQUIREMENTS." at 12053,3673.57 h60
  text "PCB MUST BEAR THE UL94V-0 UL REGISTERED MATERIAL ID NUMBER" at 12053,3557.5 h60
  text "ADDITIONAL REQUIREMENTS:" at 12025.46,3388.08 h60
  text "MICROSECTION:" at 12100.23,3280.95 h60
  text "YES" at 13005.96,3280.95 h60
  text "REQUIRED" at 13867.46,3136.62 h60
  text "BARE BOARD ELEC. TEST:" at 12100.23,3133.76 h60
  text "NONE" at 13405.96,3133.76 h60
  text "X" at 13749.46,3133.76 h60
  text "PER ORDER" at 14459.46,3133.76 h60
  text "XX MIL VIAS REQUIRE NON-CONDUCTIVE FILL AND PLANARIZE" at 12268.38,2928.82 h59
  text "XX MIL VIAS REQUIRE CONDUCTIVE FILL AND PLANARIZE" at 12276.38,2824.84 h60
  text "OUTER XX MIL TRACES REQUIRE 50 OHM SINGLE-ENDED IMPEDANCE" at 12275.39,2661.46 h58
  text "LAYER 2 & 3 (INNER LAYERS) XX MIL WIDE, XX MIL SPACE / TRACES REQUIRE 100 OHM DIFFERENTIAL IMPEDANCE" at 12267.39,2425.74 h60
  text ".Layer_Name" at 1269,675.51 h60
M11 Gerber Information:
  lines w10: 400,603.83 7000,603.83 ; 400,807.17 7002,807.17 ; 400,1010.5 400,400.5 4405,400.5 7002,400.5 7002,1010.5 400.5,1010.5 400.5,400.5 1976,400.5 ; 2865,400.5 2865,1010.5 ; 4132,807.17 4132,1010.5 ; 4972,807.17 4972,1010.5 ; 5594,394 5594,596.83
  text "ALL ARTWORK VIEWED FROM TOP SIDE" at 463.5,878.33 h60
  text "BOARD #:" at 2940,878.33 h60
  text ".PRJ_Number" at 3485.5,878.33 h60
  text "REV:" at 4330,878.33 h60
  text ".PCB_Rev" at 4621.5,878.33 h60
  text "SVN REV:" at 5168,878.33 h60
  text ".VersionControl_RevNumber" at 5674,878.33 h60
  text "LAYER NAME =" at 463.5,675.51 h60
  text "TID #:" at 2940,675 h60
  text ".TID" at 3485.5,675 h60
  text "PLOT NAME =" at 463.5,469.66 h60
  text ".plot_File_Name" at 1269,469.66 h60
  text "GENERATED    :" at 2942,469.66 h60
  text ".Print_Date" at 3811.5,469.66 h60
  text ".Print_Time" at 4540.5,469.66 h60
  text "TEXAS INSTRUMENTS" at 5805,469.66 h60
M12 Stackup:
  drawing of 191 lines, arcs and shapes, not listed
  text "Layer" at 10513.59,9408.94 h60
  text "Name" at 10923.51,9408.94 h60
  text "Material" at 11853.25,9408.94 h60
  text "Thickness" at 12713.02,9408.94 h60
  text "Constant" at 13362.85,9408.94 h60
  text "Board Layer Stack" at 13932.71,9408.94 h60
  text "Top Overlay" at 10923.51,9288.94 h60
  text "Top Solder" at 10923.51,9168.94 h60
  text "Solder Resist" at 11853.25,9168.94 h60
  text "0.40mil" at 12713.02,9168.94 h60
  text "3.5" at 13362.85,9168.94 h60
  text "1" at 10513.59,9048.94 h60
  text "F.CU" at 10923.51,9048.94 h60
  text "CF-003" at 11853.25,9048.94 h60
  text "0.71mil" at 12713.02,9048.94 h60
  text "Dielectric1" at 10923.51,8928.94 h60
  text "FR-4 High Tg" at 11853.25,8928.94 h60
  text "59.20mil" at 12713.02,8928.94 h60
  text "4.8" at 13362.85,8928.94 h60
  text "2" at 10513.59,8808.94 h60
  text "B.CU" at 10923.51,8808.94 h60
  text "CF-003" at 11853.25,8808.94 h60
  text "0.71mil" at 12713.02,8808.94 h60
  text "Bottom Solder" at 10923.51,8688.94 h60
  text "Solder Resist" at 11853.25,8688.94 h60
  text "0.40mil" at 12713.02,8688.94 h60
  text "3.5" at 13362.85,8688.94 h60
  text "Bottom Overlay" at 10923.51,8568.94 h60
  text ".Layer_Name" at 1269,675.51 h60
M13 Component Bodies Top:
  text ".Layer_Name" at 1269,675.51 h60
M14 Component Bodies Bottom:
  text ".Layer_Name" at 1269,675.51 h60
M15 Courtyards Top:
  text ".Layer_Name" at 1269,675.51 h60
M16 Courtyards Bottom:
  text ".Layer_Name" at 1269,675.51 h60
Drill Drawing:
  circle w10: c6813.28,8540.81 r16.6
  circle w10: c6813.28,8540.81 r27.67
  circle w10: c6813.28,8416.31 r27.67
  lines w10: 6785.61,7517.14 6840.94,7517.14 6840.94,7572.47 6785.61,7572.47 6785.61,7517.14 ; 6785.61,7669.31 6813.28,7641.64 6840.94,7669.31 6813.28,7696.97 6785.61,7669.31 ; 6785.61,7779.97 6799.44,7779.97 6799.44,7766.14 6827.11,7766.14 6827.11,7779.97 6840.94,7779.97 6840.94,7807.64 6827.11,7807.64 6827.11,7821.47 6799.44,7821.47 6799.44,7807.64 6785.61,7807.64 6785.61,7779.97 ; 6785.61,7890.64 6785.61,7904.47 6799.44,7918.31 6785.61,7932.14 6785.61,7945.97 6799.44,7945.97 6813.28,7932.14 6827.11,7945.97 6840.94,7945.97 6840.94,7932.14 6827.11,7918.31 6840.94,7904.47 6840.94,7890.64 6827.11,7890.64 6813.28,7904.47 6799.44,7890.64 6785.61,7890.64 ; 6785.61,8070.47 6840.94,8070.47 6813.28,8015.14 6785.61,8070.47 ; 6785.61,8153.47 6799.44,8153.47 6813.28,8139.64 6827.11,8153.47 6840.94,8153.47 6827.11,8167.31 6840.94,8181.14 6827.11,8181.14 6813.28,8194.97 6799.44,8181.14 6785.61,8181.14 6799.44,8167.31 6785.61,8153.47 ; 6785.61,8277.97 6799.44,8277.97 6799.44,8264.14 6827.11,8264.14 6827.11,8277.97 6840.94,8277.97 6840.94,8305.64 6827.11,8305.64 6827.11,8319.47 6799.44,8319.47 6799.44,8305.64 6785.61,8305.64 6785.61,8277.97 ; 6785.61,8637.64 6840.94,8637.64 6840.94,8692.97 6785.61,8692.97 6785.61,8637.64 ; 6785.61,8817.47 6840.94,8817.47 6813.28,8762.14 6785.61,8817.47 ; 6785.61,8886.64 6813.28,8900.47 6840.94,8886.64 6827.11,8914.31 6840.94,8941.97 6813.28,8928.14 6785.61,8941.97 6799.44,8914.31 6785.61,8886.64 ; 6796.68,8283.51 6804.98,8283.51 6804.98,8275.21 6821.58,8275.21 6821.58,8283.51 6829.88,8283.51 6829.88,8300.11 6821.58,8300.11 6821.58,8308.41 6804.98,8308.41 6804.98,8300.11 6796.68,8300.11 6796.68,8283.51 ; 6796.68,8648.71 6829.88,8648.71 6829.88,8681.91 6796.68,8681.91 6796.68,8648.71 ; 6796.68,8806.41 6829.88,8806.41 6813.28,8773.21 6796.68,8806.41
  lines w12: 6735.45,7479.79 9768.63,7479.79 ; 6735.45,8973.79 9768.63,8973.79 ; 7073.46,7355.29 7073.46,9098.29 ; 7405.62,7355.29 7405.62,9098.29 ; 8042.1,7355.29 8042.1,9098.29 ; 8301.3,7355.29 8301.3,9098.29 ; 8676.54,7355.29 8676.54,9098.29 ; 9202.08,7355.29 9202.08,9098.29 ; 6735.45,7355.29 9768.63,7355.29 9768.63,9098.29 6735.45,9098.29 6735.45,7355.29
  text "Symbol" at 6810.15,9011.14 h72
  text "Quantity" at 7110.81,9011.14 h72
  text "Finished Hole Size" at 7442.97,9011.14 h72
  text "Plated" at 8079.45,9011.14 h72
  text "Hole Type" at 8338.65,9011.14 h72
  text "Drill Layer Pair" at 8713.89,9011.14 h72
  text "Hole Tolerance" at 9239.43,9011.14 h72
  text "4" at 7110.81,8886.64 h60
  text "125.00mil (3.175mm)" at 7442.97,8886.64 h60
  text "NPTH" at 8079.45,8886.64 h60
  text "Round" at 8338.65,8886.64 h60
  text "F.CU - B.CU" at 8713.89,8886.64 h60
  text "163" at 7110.81,8762.14 h60
  text "7.87mil (0.200mm)" at 7442.97,8762.14 h60
  text "PTH" at 8079.45,8762.14 h60
  text "Round" at 8338.65,8762.14 h60
  text "F.CU - B.CU" at 8713.89,8762.14 h60
  text "774" at 7110.81,8637.64 h60
  text "8.00mil (0.203mm)" at 7442.97,8637.64 h60
  text "PTH" at 8079.45,8637.64 h60
  text "Round" at 8338.65,8637.64 h60
  text "F.CU - B.CU" at 8713.89,8637.64 h60
  text "22" at 7110.81,8513.14 h60
  text "17.72mil (0.450mm)" at 7442.97,8513.14 h60
  text "PTH" at 8079.45,8513.14 h60
  text "Round" at 8338.65,8513.14 h60
  text "F.CU - B.CU" at 8713.89,8513.14 h60
  text "8" at 7110.81,8388.64 h60
  text "40.00mil (1.016mm)" at 7442.97,8388.64 h60
  text "PTH" at 8079.45,8388.64 h60
  text "Round" at 8338.65,8388.64 h60
  text "F.CU - B.CU" at 8713.89,8388.64 h60
  text "40" at 7110.81,8264.14 h60
  text "40.16mil (1.020mm)" at 7442.97,8264.14 h60
  text "PTH" at 8079.45,8264.14 h60
  text "Round" at 8338.65,8264.14 h60
  text "F.CU - B.CU" at 8713.89,8264.14 h60
  text "2" at 7110.81,8139.64 h60
  text "43.31mil (1.100mm)" at 7442.97,8139.64 h60
  text "PTH" at 8079.45,8139.64 h60
  text "Round" at 8338.65,8139.64 h60
  text "F.CU - B.CU" at 8713.89,8139.64 h60
  text "16" at 7110.81,8015.14 h60
  text "49.21mil (1.250mm)" at 7442.97,8015.14 h60
  text "PTH" at 8079.45,8015.14 h60
  text "Round" at 8338.65,8015.14 h60
  text "F.CU - B.CU" at 8713.89,8015.14 h60
  text "1" at 7110.81,7890.64 h60
  text "51.00mil (1.295mm)" at 7442.97,7890.64 h60
  text "PTH" at 8079.45,7890.64 h60
  text "Round" at 8338.65,7890.64 h60
  text "F.CU - B.CU" at 8713.89,7890.64 h60
  text "4" at 7110.81,7766.14 h60
  text "51.18mil (1.300mm)" at 7442.97,7766.14 h60
  text "PTH" at 8079.45,7766.14 h60
  text "Round" at 8338.65,7766.14 h60
  text "F.CU - B.CU" at 8713.89,7766.14 h60
  text "19" at 7110.81,7641.64 h60
  text "63.00mil (1.600mm)" at 7442.97,7641.64 h60
  text "PTH" at 8079.45,7641.64 h60
  text "Round" at 8338.65,7641.64 h60
  text "F.CU - B.CU" at 8713.89,7641.64 h60
  text "1" at 7110.81,7517.14 h60
  text "118.11mil (3.000mm)" at 7442.97,7517.14 h60
  text "PTH" at 8079.45,7517.14 h60
  text "Round" at 8338.65,7517.14 h60
  text "F.CU - B.CU" at 8713.89,7517.14 h60
  text "1054 Total" at 7110.81,7392.64 h60
  text ".Layer_Name" at 1269,675.51 h60
M17 Embedded Cavity:
  text ".Layer_Name" at 1269,675.51 h60
M18 Embedded Assembly:
  text ".Layer_Name" at 1269,675.51 h60
M19 Embedded Keepout:
  text ".Layer_Name" at 1269,675.51 h60

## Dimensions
692,1134 to 1692,1134 on M2 Board Dimensions
692,1534 to 692,7534 on M2 Board Dimensions
692,1534 to 5192,1534 on M2 Board Dimensions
